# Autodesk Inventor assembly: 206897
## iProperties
Created: 2008-01
Part Number: 206897
Document SubType Name: Assembly
Designer: jjohnson
Mass: 119.186 g
Surface Area: 559.788 cm^2
Volume: 62.8758 cm^3
Density: 1.89557 g/cm^3
Author: jjohnson
